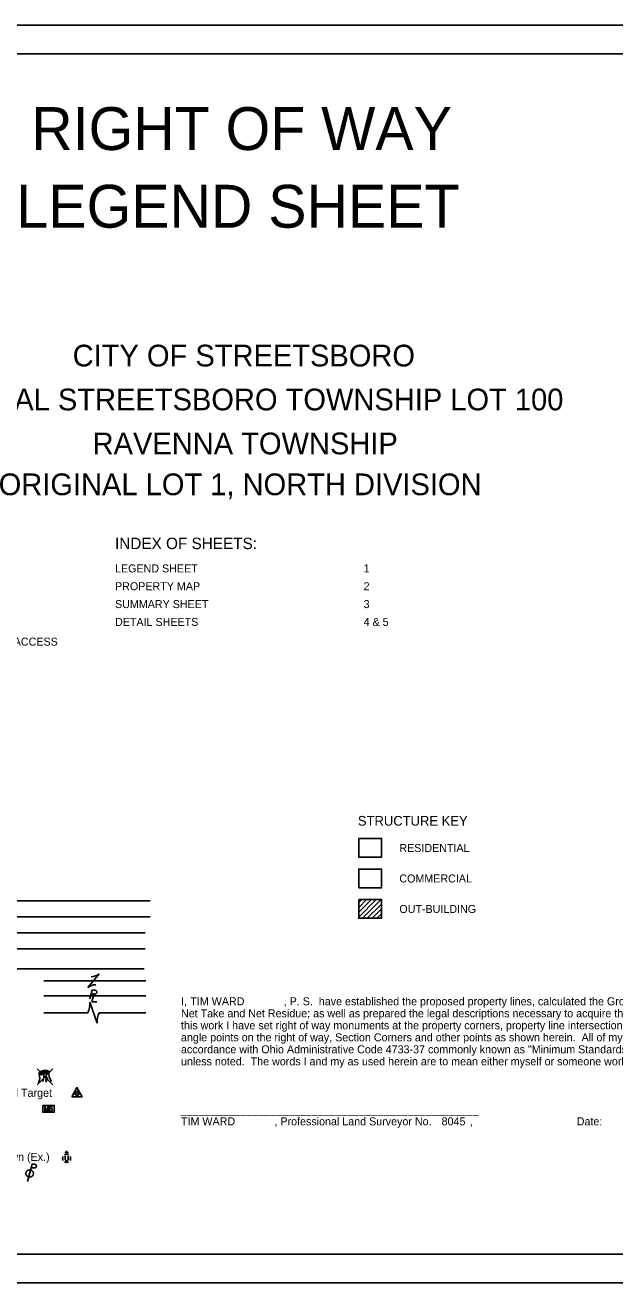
# Model space of a CAD drawing. Extents: x 0 to 34, y 0 to 22.
# Drawn here: x 12.12 to 22.43, y 0 to 22 of the extents above; entities that cross this region are included whole.
import ezdxf

# ---------------------------------------------------------------- set-up
doc = ezdxf.new("R2010")
doc.units = 0
for name, color, linetype in [('SC_Shading1', 7, 'Continuous'), ('SH_Border', 7, 'Continuous'), ('SH_Cut_Line', 7, 'Continuous'), ('SH_Data', 7, 'Continuous'), ('SH_Text', 7, 'Continuous')]:
    doc.layers.add(name, color=color, linetype=linetype)

msp = doc.modelspace()

# ---------------------------------------------------------------- linework, layer by layer
at = {"layer": 'SC_Shading1'}
msp.add_lwpolyline([(17.954, 6.912), (18.351, 6.912), (18.351, 7.238), (17.954, 7.238)], close=True, dxfattribs=at)
at = {"layer": 'SH_Border'}
msp.add_lwpolyline([(1.5, 21.5), (33.5, 21.5), (33.5, 0.5), (1.5, 0.5)], close=True, dxfattribs=at)
at = {"layer": 'SH_Cut_Line'}
msp.add_lwpolyline([(0, 0), (34, 0), (34, 22), (0, 22)], close=True, dxfattribs=at)
at = {"layer": 'SH_Text'}
for p, q in [((10.82, 6.684), (14.304, 6.684)), ((17.954, 6.702), (17.955, 6.703)), ((17.954, 6.652), (18.005, 6.703)), ((17.954, 6.567), (18.09, 6.703)), ((17.954, 6.482), (18.174, 6.703)), ((17.954, 6.397), (18.259, 6.703)), ((18.018, 6.377), (18.344, 6.703)), ((18.103, 6.377), (18.351, 6.625)), ((10.82, 6.404), (14.304, 6.404)), ((17.954, 6.382), (17.958, 6.377)), ((18.187, 6.377), (18.351, 6.54)), ((18.272, 6.377), (18.351, 6.456)), ((10.32, 6.124), (14.22, 6.124)), ((10.32, 5.844), (14.22, 5.844)), ((9.852, 5.494), (14.202, 5.494)), ((12.45, 5.284), (14.232, 5.284)), ((13.215, 5.164), (13.415, 5.404)), ((13.315, 5.284), (13.315, 5.284)), ((12.45, 5.02), (14.232, 5.02)), ((13.25, 4.908), (13.38, 4.54)), ((13.273, 5.049), (13.338, 5.049)), ((13.313, 5.018), (13.313, 5.018)), ((12.45, 4.724), (13.215, 4.724)), ((13.315, 4.724), (13.315, 4.724)), ((13.415, 4.724), (14.232, 4.724)), ((12.329, 3.743), (12.607, 3.465)), ((12.607, 3.743), (12.329, 3.465)), ((12.468, 3.604), (12.468, 3.604)), ((12.468, 3.604), (12.468, 3.604)), ((12.529, 3.044), (12.529, 3.044)), ((12.878, 2.28), (12.814, 2.28)), ((12.819, 2.221), (12.819, 2.152)), ((12.846, 2.248), (12.846, 2.311)), ((12.873, 2.221), (12.873, 2.152)), ((12.242, 2.074), (12.162, 1.774)), ((12.225, 2.01), (12.285, 2.01)), ((12.242, 2.074), (12.285, 2.074)), ((12.846, 2.178), (12.846, 2.178))]:
    msp.add_line(p, q, dxfattribs=at)
for points in [[(17.954, 7.774), (18.351, 7.774), (18.351, 7.448), (17.954, 7.448)], [(17.954, 6.703), (18.351, 6.703), (18.351, 6.377), (17.954, 6.377)], [(12.937, 3.254), (13.117, 3.254), (13.027, 3.415)], [(12.429, 3.105), (12.629, 3.105), (12.629, 2.983), (12.429, 2.983)]]:
    msp.add_lwpolyline(points, close=True, dxfattribs=at)
for points in [[(13.252, 4.969), (13.291, 5.118), (13.343, 5.118)], [(13.327, 5.066), (13.287, 4.918), (13.374, 4.918)], [(12.464, 3.004), (12.464, 3.084), (12.493, 3.004), (12.521, 3.084), (12.521, 3.004)], [(12.58, 3.048), (12.583, 3.051), (12.585, 3.053), (12.586, 3.055), (12.587, 3.056), (12.588, 3.058), (12.589, 3.06), (12.59, 3.065), (12.59, 3.067), (12.59, 3.069), (12.589, 3.073), (12.588, 3.076), (12.586, 3.078), (12.583, 3.081), (12.581, 3.082), (12.579, 3.083), (12.576, 3.084), (12.545, 3.084), (12.545, 3.004), (12.58, 3.004), (12.584, 3.007), (12.588, 3.01), (12.591, 3.015), (12.593, 3.021), (12.594, 3.026), (12.594, 3.03), (12.593, 3.034), (12.59, 3.039), (12.587, 3.043), (12.58, 3.048), (12.545, 3.048)]]:
    msp.add_lwpolyline(points, dxfattribs=at)
for centre, radius in [((13.027, 3.312), 0.035), ((13.027, 3.312), 0.008), ((12.199, 1.914), 0.065)]:
    msp.add_circle(centre, radius, dxfattribs=at)
for centre, radius, start, end in [((13.257, 5.619), 0.267, 273.6945, 306.337), ((13.373, 4.949), 0.267, 93.6945, 126.337), ((13.338, 5.084), 0.0345, 270.471, 81.3281), ((12.918, 4.876), 0.334, 332.9422, 5.5848), ((13.712, 4.573), 0.334, 152.9422, 185.5848), ((12.176, 3.587), 0.2, 331.5338, 20.9269), ((12.192, 3.605), 0.253, 340.7938, 3.5481), ((12.663, 3.564), 0.182, 178.7926, 197.1224), ((12.793, 3.707), 0.316, 194.9653, 212.1216), ((12.748, 3.661), 0.215, 171.4106, 219.9194), ((12.846, 2.178), 0.07, 150.0184, 209.9816), ((12.846, 2.178), 0.07, 60.0184, 120.0157), ((12.846, 2.178), 0.07, 330.0184, 29.9816), ((12.285, 2.042), 0.0319, 268.8767, 91.1233), ((12.846, 2.178), 0.07, 239.9843, 299.9816), ((12.846, 2.165), 0.03, 205.1924, 334.8076)]:
    msp.add_arc(centre, radius, start, end, dxfattribs=at)
for major_axis in [(0.0868, 0.0187), (0.0651, 0.0141), (0.0488, 0.0105), (0.0275, 0.0059), (0.0154, 0.0033)]:
    msp.add_ellipse((12.449, 3.68), major_axis=major_axis, ratio=0.36865, dxfattribs=at)

# ---------------------------------------------------------------- texts
at = {"layer": 'SH_Data'}
for s, height, p in [('RIGHT OF WAY', 0.75, (12.227, 19.816)), ('LEGEND SHEET', 0.75, (11.968, 18.457)), ('CITY OF STREETSBORO', 0.38, (12.951, 16.03)), ('ORIGINAL STREETSBORO TOWNSHIP LOT 100', 0.38, (10.124, 15.262)), ('RAVENNA TOWNSHIP', 0.38, (13.3, 14.493)), ('ORIGINAL LOT 1, NORTH DIVISION', 0.38, (11.658, 13.778)), ('INDEX OF SHEETS:', 0.2, (13.692, 12.835)), ('LEGEND SHEET                       ', 0.14, (13.692, 12.427)), ('1     ', 0.14, (18.038, 12.427)), ('PROPERTY MAP                       ', 0.14, (13.692, 12.115)), ('2     ', 0.14, (18.038, 12.115)), ('SUMMARY SHEET                      ', 0.14, (13.692, 11.803)), ('3     ', 0.14, (18.038, 11.803)), ('DETAIL SHEETS', 0.14, (13.692, 11.491)), ('4 & 5', 0.14, (18.038, 11.491))]:
    msp.add_text(s, height=height, dxfattribs=at).set_placement(p)
at = {"layer": 'SH_Text'}
for s, height, p in [('WL = FEE SIMPLE WITH LIMITATION OF ACCESS', 0.14, (8.327, 11.146)), ('STRUCTURE KEY', 0.17, (17.938, 7.997)), ('RESIDENTIAL', 0.14, (18.663, 7.537)), ('COMMERCIAL', 0.14, (18.663, 7.003)), ('OUT-BUILDING', 0.14, (18.663, 6.47)), ('I, ', 0.14, (14.845, 4.855)), ('TIM WARD            ', 0.14, (15.008, 4.855)), (', P. S.  have established the proposed property lines, calculated the Gross Take, Present Roadway Occupied (PRO),', 0.14, (16.641, 4.855)), ('Net Take and Net Residue; as well as prepared the legal descriptions necessary to acquire these parcels as shown herein. As a part of', 0.14, (14.845, 4.645)), ('this work I have set right of way monuments at the property corners, property line intersections, points along the right of way and/or', 0.14, (14.845, 4.435)), ('angle points on the right of way, Section Corners and other points as shown herein.  All of my work contained herein was conducted in', 0.14, (14.845, 4.225)), ('accordance with Ohio Administrative Code 4733-37 commonly known as "Minimum Standards for Boundary Surveys in the State of Ohio"', 0.14, (14.845, 4.015)), ('unless noted.  The words I and my as used herein are to mean either myself or someone working under my direct supervision.', 0.14, (14.845, 3.805)), ('Wetland (Pr)         , Grass (Pr)            , Aerial Target    ', 0.14, (8.304, 3.254)), ('__________________________________________________', 0.14, (14.845, 2.965)), ('TIM WARD            ', 0.14, (14.845, 2.755)), (', Professional Land Surveyor No. ', 0.14, (16.479, 2.755)), ('8045 ', 0.14, (19.402, 2.755)), (',                                   Date: ', 0.14, (19.892, 2.755)), ('Water Valve (Ex)         , Utility Valve Unknown (Ex.)', 0.14, (8.304, 2.134))]:
    msp.add_text(s, height=height, dxfattribs=at).set_placement(p)

doc.saveas('drawing.dxf')
